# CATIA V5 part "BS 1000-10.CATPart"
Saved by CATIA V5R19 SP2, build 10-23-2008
Part number: BS 1000-10
Bounding box of the stored display mesh (mm): x -24.865 to 24.865, y -24.997 to 24.997, z 0 to 58
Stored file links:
  C:\Users\Bora\Desktop\3D Katı model\BS serisi\BS 1000\BS 1000-10.CATPart
  C:\Program Files\Dassault Systemes\B19\intel_a\reffiles\standard\MetricThickPitch.txt
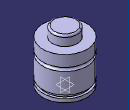
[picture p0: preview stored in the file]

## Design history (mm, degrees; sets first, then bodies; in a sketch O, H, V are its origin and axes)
Body1 (main body)
  Sketch1 on yz-plane, origin (0, 0, 0), H (0, 1, 0), V (0, 0, 1)
    point P1 (14, 56)
    point P4 (25, 34.5)
    point P5 (25, 30.5)
    point P9 (25, 34.5)
    point P10 (25, 30.5)
    point P11 (14, 56)
    point P13 (22.5, 4)
    point P15 (22.5, 4)
    line L1 (14, 56) -> (14, 47)
    line L2 (25, 47) -> (25, 34.5)
    line L3 (25, 30.5) -> (25, 7.5)
    line L4 (25, 4) -> (25, 0)
    arc A1 centre (25, 32.5) radius 2 from (25, 34.5) to (25, 30.5) ccw
    arc A2 centre (12, 56) radius 2 from (14, 56) to (12, 58) ccw
    line L5 (22.5, 7.5) -> (22.5, 4)
    line L6 (12, 58) -> (0, 58)
    point P16 (0, 58)
    line L7 (14, 47) -> (25, 47)
    line L8 (22.5, 7.5) -> (25, 7.5)
    line L9 (22.5, 4) -> (25, 4)
    line L10 (25, 0) -> (0, 0)
    coincidence: P16 V, P1 P11, P4 P9, P5 P10, P13 P15
    tangency: L6 A2
    horizontal: L7 H, L8 H, L9 H, L10 H
  Shaft1: profile Sketch1, axis Sketch1.V, angle 360
  Sketch2 on face of Shaft1 from Sketch1.L10, origin (0, 0, 0), H (1, 0, 0), V (0, -1, 0)
    point P1 (10, 0)
    distance P1 V = 10
  Hole1: placed by Sketch2, at (10, 0, 0) direction (0, 0, 1), diameter 6.647, depth 6, threaded "M8", thread diameter 8, thread depth 6, pitch 1.25
  CircPattern1: of Hole1, instances 2, angular step 180, axis from xy-plane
